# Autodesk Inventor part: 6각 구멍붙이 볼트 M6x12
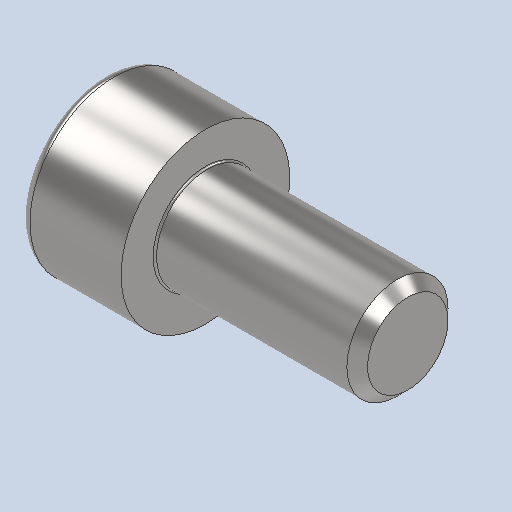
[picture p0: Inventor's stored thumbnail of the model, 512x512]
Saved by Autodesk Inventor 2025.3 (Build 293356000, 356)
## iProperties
Created: 2026-01
Part Number: 6각 구멍붙이 볼트 M6x12
Material: 강철, 연강
Description: 6각머리 태핑 나사
Document SubType Name: Modeling
Designer: PC-13
Density: 7.85 g/cm^3
Appearance: 기본값
Author: jhkim
Sending System: Autodesk Inventor 2026
Preprocessor: ST-DEVELOPER v20.1
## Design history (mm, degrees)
feature "Solid1"
node "솔리드1"
